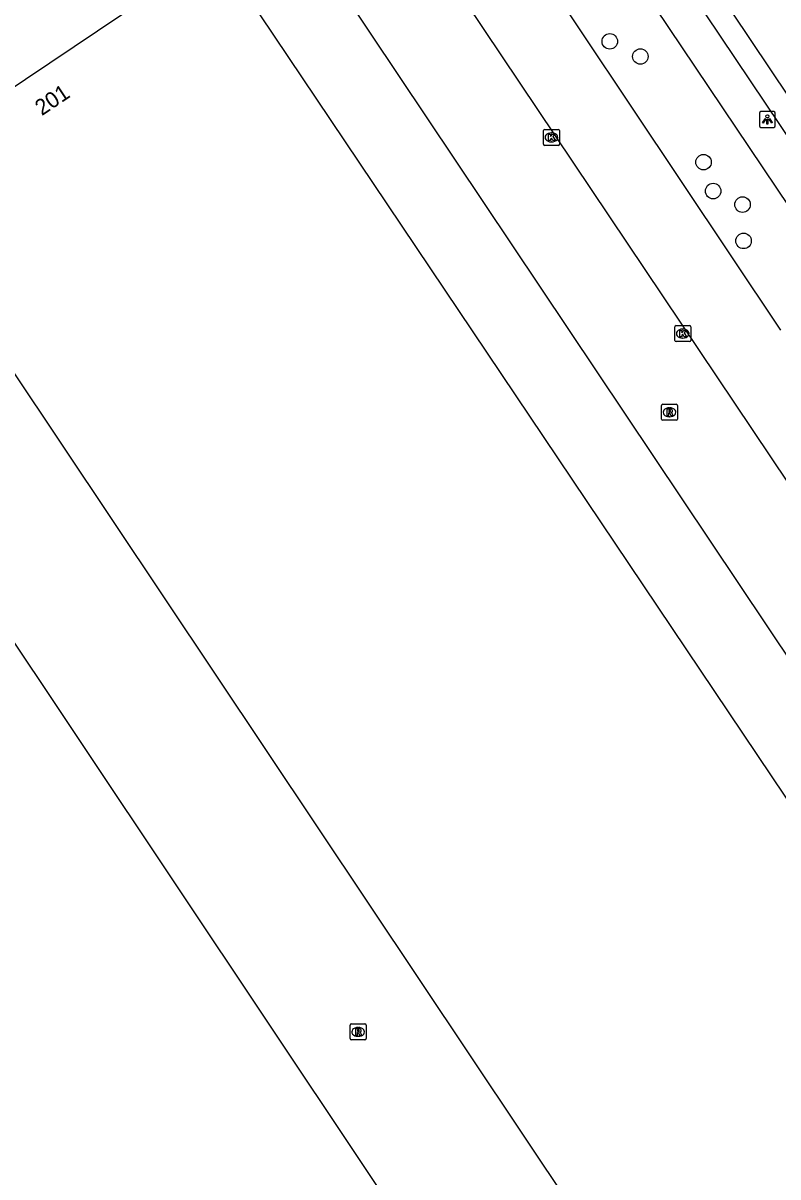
# Model space of a CAD drawing. Extents: x 158797 to 159887, y 384318 to 385255.
# Drawn here: x 159059.5 to 159107.1, y 384456.6 to 384529.2 of the extents above; entities that cross this region are included whole.
import ezdxf

# ---------------------------------------------------------------- set-up
doc = ezdxf.new("R2010")
doc.units = 0
for name, color, linetype in [('IMGEO_Boom', 7, 'Continuous'), ('IMGEO_Groenvoorziening', 7, 'Continuous'), ('IMGEO_Kolk', 7, 'Continuous'), ('IMGEO_Lichtpunt', 7, 'Continuous'), ('IMGEO_Pand', 7, 'Continuous'), ('IMGEO_Pand_nummerreeks', 7, 'Continuous'), ('IMGEO_Parkeervlak_open', 7, 'Continuous'), ('IMGEO_Rijbaan_lokaal_open', 7, 'Continuous'), ('IMGEO_Rioolput', 7, 'Continuous'), ('IMGEO_Voetpad_open', 7, 'Continuous')]:
    doc.layers.add(name, color=color, linetype=linetype)

msp = doc.modelspace()

# ---------------------------------------------------------------- linework, layer by layer
at = {"layer": 'IMGEO_Boom'}
for centre in [(159096.504, 384528.079), (159098.43, 384527.126), (159102.409, 384520.471), (159103.014, 384518.651), (159104.865, 384517.798), (159104.93, 384515.512)]:
    msp.add_circle(centre, 0.489, dxfattribs=at)
at = {"layer": 'IMGEO_Groenvoorziening'}
msp.add_lwpolyline([(159129.89, 384484.816), (159089.196, 384545.377)], dxfattribs=at)
at = {"layer": 'IMGEO_Kolk'}
for p, q in [((159092.329, 384521.603), (159092.329, 384522.455)), ((159092.404, 384522.529), (159093.256, 384522.529)), ((159092.817, 384522.309), (159092.842, 384522.309)), ((159093.33, 384522.455), (159093.33, 384521.603)), ((159093.256, 384521.529), (159092.404, 384521.529)), ((159092.84, 384521.749), (159092.815, 384521.749)), ((159100.6, 384509.247), (159100.6, 384510.099)), ((159100.675, 384510.173), (159101.527, 384510.173)), ((159101.088, 384509.953), (159101.113, 384509.953)), ((159101.601, 384510.099), (159101.601, 384509.247)), ((159101.527, 384509.173), (159100.675, 384509.173)), ((159101.111, 384509.393), (159101.086, 384509.393))]:
    msp.add_line(p, q, dxfattribs=at)
for points in [[(159092.329, 384521.603), (159092.329, 384522.455)], [(159092.404, 384522.529), (159093.256, 384522.529)], [(159092.65, 384522.229), (159092.773, 384522.229), (159092.773, 384522.078), (159092.903, 384522.229), (159093.067, 384522.229), (159092.921, 384522.078), (159093.074, 384521.829), (159092.922, 384521.829), (159092.837, 384521.993), (159092.773, 384521.926), (159092.773, 384521.829), (159092.65, 384521.829), (159092.65, 384522.229)], [(159093.33, 384522.455), (159093.33, 384521.603)], [(159093.256, 384521.529), (159092.404, 384521.529)], [(159100.6, 384509.247), (159100.6, 384510.099)], [(159100.675, 384510.173), (159101.527, 384510.173)], [(159100.921, 384509.873), (159101.044, 384509.873), (159101.044, 384509.722), (159101.174, 384509.873), (159101.338, 384509.873), (159101.192, 384509.722), (159101.345, 384509.473), (159101.193, 384509.473), (159101.108, 384509.637), (159101.044, 384509.57), (159101.044, 384509.473), (159100.921, 384509.473), (159100.921, 384509.873)], [(159101.601, 384510.099), (159101.601, 384509.247)], [(159101.527, 384509.173), (159100.675, 384509.173)]]:
    msp.add_lwpolyline(points, dxfattribs=at)
for centre, start, end in [((159092.406, 384522.453), 91.55205, 178.44795), ((159092.406, 384522.453), 91.55205, 178.44795), ((159093.254, 384522.453), 1.55205, 88.44795), ((159093.254, 384522.453), 1.55205, 88.44795), ((159092.406, 384521.605), 181.55205, 268.44795), ((159092.406, 384521.605), 181.55205, 268.44795), ((159093.254, 384521.605), 271.55205, 358.44795), ((159093.254, 384521.605), 271.55205, 358.44795), ((159100.677, 384510.097), 91.55205, 178.44795), ((159100.677, 384510.097), 91.55205, 178.44795), ((159101.525, 384510.097), 1.55205, 88.44795), ((159101.525, 384510.097), 1.55205, 88.44795), ((159100.677, 384509.249), 181.55205, 268.44795), ((159100.677, 384509.249), 181.55205, 268.44795), ((159101.525, 384509.249), 271.55205, 358.44795), ((159101.525, 384509.249), 271.55205, 358.44795)]:
    msp.add_arc(centre, 0.0765, start, end, dxfattribs=at)
for centre, major_axis, ratio, start_param, end_param in [((159092.816, 384522.029), (-0.387, 0.002), 0.722429, 4.712389, 7.853982), ((159092.841, 384522.029), (-0.39, 0.002), 0.717154, 1.570796, 4.712389), ((159101.087, 384509.673), (-0.387, 0.002), 0.722429, 4.712389, 7.853982), ((159101.112, 384509.673), (-0.39, 0.002), 0.717154, 1.570796, 4.712389)]:
    msp.add_ellipse(centre, major_axis=major_axis, ratio=ratio, start_param=start_param, end_param=end_param, dxfattribs=at)
at = {"layer": 'IMGEO_Lichtpunt'}
for p, q in [((159106.831, 384523.655), (159106.023, 384523.655)), ((159106.831, 384523.655), (159106.023, 384523.655)), ((159105.929, 384523.56), (159105.929, 384522.753)), ((159105.929, 384523.56), (159105.929, 384522.753)), ((159106.925, 384522.753), (159106.925, 384523.56)), ((159106.925, 384522.753), (159106.925, 384523.56)), ((159106.023, 384522.659), (159106.831, 384522.659)), ((159106.023, 384522.659), (159106.831, 384522.659))]:
    msp.add_line(p, q, dxfattribs=at)
for points in [[(159106.303, 384523.224), (159106.342, 384523.196), (159106.154, 384522.934), (159106.116, 384522.961), (159106.303, 384523.224)], [(159106.405, 384523.176), (159106.452, 384523.176), (159106.452, 384522.854), (159106.405, 384522.854), (159106.405, 384523.176)], [(159106.515, 384523.196), (159106.553, 384523.223), (159106.74, 384522.961), (159106.701, 384522.933), (159106.515, 384523.196)]]:
    msp.add_lwpolyline(points, dxfattribs=at)
msp.add_circle((159106.428, 384523.358), 0.0994, dxfattribs=at)
for centre, start, end in [((159106.023, 384523.56), 90, 180), ((159106.023, 384523.56), 90, 180), ((159106.831, 384523.56), 0, 90), ((159106.831, 384523.56), 0, 90), ((159106.023, 384522.753), 180, 270), ((159106.023, 384522.753), 180, 270), ((159106.831, 384522.753), 270, 0), ((159106.831, 384522.753), 270, 360)]:
    msp.add_arc(centre, 0.0946, start, end, dxfattribs=at)
at = {"layer": 'IMGEO_Pand'}
for points in [[(159071.774, 384533.799), (159050.67, 384519.624)], [(159126.029, 384461.936), (159121.905, 384459.166), (159071.774, 384533.799)], [(159050.67, 384519.624), (159058.757, 384507.518), (159100.592, 384444.894), (159099.734, 384444.322), (159105.622, 384435.536)], [(159099.728, 384431.577), (159096.595, 384436.272), (159093.851, 384440.4), (159092.757, 384439.671), (159051.335, 384501.662), (159042.827, 384514.395)]]:
    msp.add_lwpolyline(points, dxfattribs=at)
at = {"layer": 'IMGEO_Parkeervlak_open'}
msp.add_lwpolyline([(159085.318, 384542.737), (159107.263, 384509.883)], dxfattribs=at)
at = {"layer": 'IMGEO_Rijbaan_lokaal_open'}
for points in [[(159125.843, 384482.068), (159121.763, 384479.19), (159114.556, 384490.118), (159081.78, 384538.994), (159081.166, 384539.91)], [(159076.06, 384536.619), (159126.029, 384461.936)]]:
    msp.add_lwpolyline(points, dxfattribs=at)
at = {"layer": 'IMGEO_Rioolput'}
for p, q in [((159099.764, 384504.293), (159099.764, 384505.145)), ((159099.839, 384505.219), (159100.691, 384505.219)), ((159100.252, 384504.999), (159100.277, 384504.999)), ((159100.765, 384505.145), (159100.765, 384504.293)), ((159100.691, 384504.219), (159099.839, 384504.219)), ((159100.275, 384504.439), (159100.25, 384504.439)), ((159080.226, 384466.193), (159081.078, 384466.193)), ((159080.151, 384465.267), (159080.151, 384466.119)), ((159080.639, 384465.973), (159080.664, 384465.973)), ((159081.152, 384466.119), (159081.152, 384465.267)), ((159081.078, 384465.193), (159080.226, 384465.193)), ((159080.662, 384465.413), (159080.637, 384465.413))]:
    msp.add_line(p, q, dxfattribs=at)
for points in [[(159099.764, 384504.293), (159099.764, 384505.145)], [(159099.839, 384505.219), (159100.691, 384505.219)], [(159100.353, 384504.917), (159100.101, 384504.919), (159100.101, 384504.519)], [(159100.101, 384504.519), (159100.225, 384504.519), (159100.225, 384504.681), (159100.236, 384504.681)], [(159100.279, 384504.838), (159100.225, 384504.838), (159100.225, 384504.757)], [(159100.225, 384504.757), (159100.277, 384504.757)], [(159100.765, 384505.145), (159100.765, 384504.293)], [(159100.691, 384504.219), (159099.839, 384504.219)], [(159100.283, 384504.652), (159100.354, 384504.519), (159100.494, 384504.519), (159100.429, 384504.645)], [(159080.226, 384466.193), (159081.078, 384466.193)], [(159080.151, 384465.267), (159080.151, 384466.119)], [(159080.74, 384465.891), (159080.488, 384465.893), (159080.488, 384465.493)], [(159080.488, 384465.493), (159080.612, 384465.493), (159080.612, 384465.655), (159080.623, 384465.655)], [(159080.666, 384465.812), (159080.612, 384465.812), (159080.612, 384465.731)], [(159080.612, 384465.731), (159080.664, 384465.731)], [(159080.67, 384465.626), (159080.741, 384465.493), (159080.881, 384465.493), (159080.816, 384465.619)], [(159081.152, 384466.119), (159081.152, 384465.267)], [(159081.078, 384465.193), (159080.226, 384465.193)]]:
    msp.add_lwpolyline(points, dxfattribs=at)
for centre, radius, start, end in [((159099.841, 384505.143), 0.0765, 91.55205, 178.44795), ((159099.841, 384505.143), 0.0765, 91.55205, 178.44795), ((159100.235, 384504.628), 0.0533, 26.02933, 88.69889), ((159100.261, 384504.946), 0.19, 274.7715, 282.96867), ((159100.285, 384504.742), 0.0964, 77.00612, 93.18647), ((159100.299, 384504.799), 0.0378, 276.66336, 79.67722), ((159100.352, 384504.807), 0.109, 350.36119, 89.41601), ((159100.35, 384504.807), 0.112, 277.58423, 350.98172), ((159100.334, 384504.592), 0.108, 29.51342, 73.79051), ((159100.689, 384505.143), 0.0765, 1.55205, 88.44795), ((159100.689, 384505.143), 0.0765, 1.55205, 88.44795), ((159099.841, 384504.295), 0.0765, 181.55205, 268.44795), ((159099.841, 384504.295), 0.0765, 181.55205, 268.44795), ((159100.689, 384504.295), 0.0765, 271.55205, 358.44795), ((159100.689, 384504.295), 0.0765, 271.55205, 358.44795), ((159080.228, 384466.117), 0.0765, 91.55205, 178.44795), ((159080.228, 384466.117), 0.0765, 91.55205, 178.44795), ((159081.076, 384466.117), 0.0765, 1.55205, 88.44795), ((159081.076, 384466.117), 0.0765, 1.55205, 88.44795), ((159080.622, 384465.602), 0.0533, 26.02933, 88.69889), ((159080.648, 384465.92), 0.19, 274.7715, 282.96867), ((159080.672, 384465.716), 0.0964, 77.00612, 93.18647), ((159080.686, 384465.773), 0.0378, 276.66336, 79.67722), ((159080.739, 384465.781), 0.109, 350.36119, 89.41601), ((159080.737, 384465.781), 0.112, 277.58423, 350.98172), ((159080.721, 384465.566), 0.108, 29.51342, 73.79051), ((159080.228, 384465.269), 0.0765, 181.55205, 268.44795), ((159080.228, 384465.269), 0.0765, 181.55205, 268.44795), ((159081.076, 384465.269), 0.0765, 271.55205, 358.44795), ((159081.076, 384465.269), 0.0765, 271.55205, 358.44795)]:
    msp.add_arc(centre, radius, start, end, dxfattribs=at)
for centre, major_axis, ratio, start_param, end_param in [((159100.251, 384504.719), (-0.387, 0.002), 0.722429, 4.712389, 7.853982), ((159100.276, 384504.719), (-0.39, 0.002), 0.717154, 1.570796, 4.712389), ((159080.638, 384465.693), (-0.387, 0.002), 0.722429, 4.712389, 7.853982), ((159080.663, 384465.693), (-0.39, 0.002), 0.717154, 1.570796, 4.712389)]:
    msp.add_ellipse(centre, major_axis=major_axis, ratio=ratio, start_param=start_param, end_param=end_param, dxfattribs=at)
at = {"layer": 'IMGEO_Voetpad_open'}
for points in [[(159146.803, 384466.42), (159092.403, 384547.537), (159106.711, 384557.186), (159108.605, 384554.36)], [(159089.196, 384545.377), (159091.171, 384546.721), (159131.847, 384486.145)]]:
    msp.add_lwpolyline(points, dxfattribs=at)

# ---------------------------------------------------------------- texts
at = {"layer": 'IMGEO_Pand_nummerreeks'}
msp.add_text('201', height=1, rotation=33.89045, dxfattribs=at).set_placement((159060.725, 384523.365))

doc.saveas('drawing.dxf')
